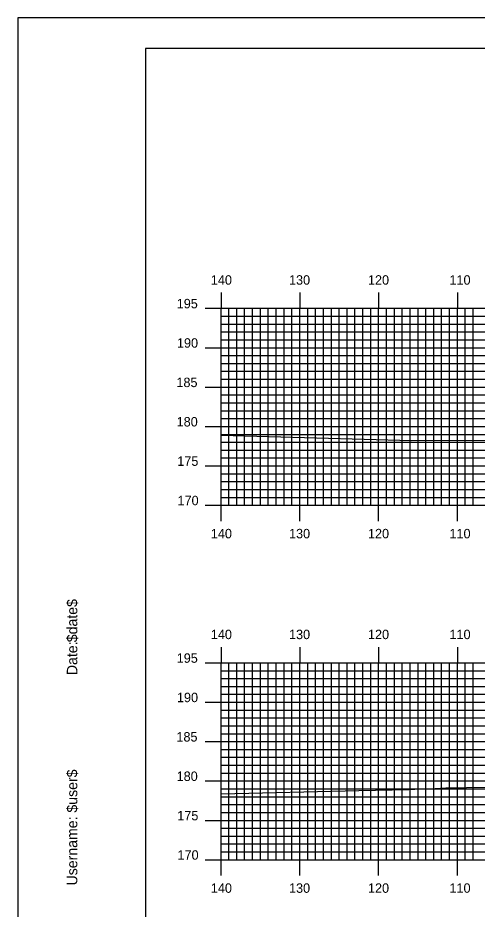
# Model space of a CAD drawing. Extents: x 1824360 to 1824703, y 442591 to 442811.
# Drawn here: x 1824359.5 to 1824417.8, y 442697.4 to 442810.5 of the extents above; entities that cross this region are included whole.
import ezdxf

# ---------------------------------------------------------------- set-up
doc = ezdxf.new("R2010")
doc.units = 0
for name, color, linetype in [('BORDER', 7, 'Continuous'), ('H_V ANNOTATION', 7, 'Continuous'), ('MAJOR', 7, 'Continuous'), ('MINOR', 7, 'Continuous'), ('PLOT BOUNDARY', 7, 'Continuous'), ('S_Roadway_Centerline', 7, 'Continuous')]:
    doc.layers.add(name, color=color, linetype=linetype)

msp = doc.modelspace()

# ---------------------------------------------------------------- linework, layer by layer
at = {"layer": 'BORDER'}
msp.add_lwpolyline([(1824375.73, 442596.67), (1824695.73, 442596.67), (1824695.73, 442806.67), (1824375.73, 442806.67)], close=True, dxfattribs=at)
at = {"layer": 'MAJOR'}
for p, q in [((1824385.33, 442775.67), (1824385.33, 442773.67)), ((1824395.33, 442775.67), (1824395.33, 442773.67)), ((1824405.33, 442775.67), (1824405.33, 442773.67)), ((1824415.33, 442775.67), (1824415.33, 442773.67)), ((1824383.33, 442773.67), (1824385.33, 442773.67)), ((1824385.33, 442773.67), (1824665.33, 442773.67)), ((1824385.33, 442748.67), (1824385.33, 442773.67)), ((1824385.33, 442748.67), (1824385.33, 442773.67)), ((1824385.33, 442773.67), (1824665.33, 442773.67)), ((1824395.33, 442748.67), (1824395.33, 442773.67)), ((1824405.33, 442748.67), (1824405.33, 442773.67)), ((1824415.33, 442748.67), (1824415.33, 442773.67)), ((1824383.33, 442768.67), (1824385.33, 442768.67)), ((1824385.33, 442768.67), (1824665.33, 442768.67)), ((1824383.33, 442763.67), (1824385.33, 442763.67)), ((1824385.33, 442763.67), (1824665.33, 442763.67)), ((1824383.33, 442758.67), (1824385.33, 442758.67)), ((1824385.33, 442758.67), (1824665.33, 442758.67)), ((1824383.33, 442753.67), (1824385.33, 442753.67)), ((1824385.33, 442753.67), (1824665.33, 442753.67)), ((1824383.33, 442748.67), (1824385.33, 442748.67)), ((1824385.33, 442748.67), (1824665.33, 442748.67)), ((1824385.33, 442748.67), (1824665.33, 442748.67)), ((1824385.33, 442746.66), (1824385.33, 442748.67)), ((1824395.33, 442746.66), (1824395.33, 442748.67)), ((1824405.33, 442746.66), (1824405.33, 442748.67)), ((1824415.33, 442746.66), (1824415.33, 442748.67)), ((1824385.33, 442730.67), (1824385.33, 442728.67)), ((1824395.33, 442730.67), (1824395.33, 442728.67)), ((1824405.33, 442730.67), (1824405.33, 442728.67)), ((1824415.33, 442730.67), (1824415.33, 442728.67)), ((1824383.33, 442728.67), (1824385.33, 442728.67)), ((1824385.33, 442728.67), (1824665.33, 442728.67)), ((1824385.33, 442703.67), (1824385.33, 442728.67)), ((1824385.33, 442703.67), (1824385.33, 442728.67)), ((1824385.33, 442728.67), (1824665.33, 442728.67)), ((1824395.33, 442703.67), (1824395.33, 442728.67)), ((1824405.33, 442703.67), (1824405.33, 442728.67)), ((1824415.33, 442703.67), (1824415.33, 442728.67)), ((1824383.33, 442723.67), (1824385.33, 442723.67)), ((1824385.33, 442723.67), (1824665.33, 442723.67)), ((1824383.33, 442718.67), (1824385.33, 442718.67)), ((1824385.33, 442718.67), (1824665.33, 442718.67)), ((1824383.33, 442713.67), (1824385.33, 442713.67)), ((1824385.33, 442713.67), (1824665.33, 442713.67)), ((1824383.33, 442708.67), (1824385.33, 442708.67)), ((1824385.33, 442708.67), (1824665.33, 442708.67)), ((1824383.33, 442703.67), (1824385.33, 442703.67)), ((1824385.33, 442703.67), (1824665.33, 442703.67)), ((1824385.33, 442703.67), (1824665.33, 442703.67)), ((1824385.33, 442701.66), (1824385.33, 442703.67)), ((1824395.33, 442701.66), (1824395.33, 442703.67)), ((1824405.33, 442701.66), (1824405.33, 442703.67)), ((1824415.33, 442701.66), (1824415.33, 442703.67))]:
    msp.add_line(p, q, dxfattribs=at)
at = {"layer": 'MINOR'}
for p, q in [((1824385.33, 442772.67), (1824665.33, 442772.67)), ((1824385.33, 442772.67), (1824387.34, 442772.67)), ((1824386.33, 442748.67), (1824386.33, 442773.67)), ((1824387.33, 442748.67), (1824387.33, 442773.67)), ((1824388.33, 442748.67), (1824388.33, 442773.67)), ((1824389.33, 442748.67), (1824389.33, 442773.67)), ((1824390.33, 442748.67), (1824390.33, 442773.67)), ((1824391.33, 442748.67), (1824391.33, 442773.67)), ((1824392.33, 442748.67), (1824392.33, 442773.67)), ((1824393.33, 442748.67), (1824393.33, 442773.67)), ((1824394.33, 442748.67), (1824394.33, 442773.67)), ((1824396.33, 442748.67), (1824396.33, 442773.67)), ((1824397.33, 442748.67), (1824397.33, 442773.67)), ((1824398.33, 442748.67), (1824398.33, 442773.67)), ((1824399.33, 442748.67), (1824399.33, 442773.67)), ((1824400.33, 442748.67), (1824400.33, 442773.67)), ((1824401.33, 442748.67), (1824401.33, 442773.67)), ((1824402.33, 442748.67), (1824402.33, 442773.67)), ((1824403.33, 442748.67), (1824403.33, 442773.67)), ((1824404.33, 442748.67), (1824404.33, 442773.67)), ((1824406.33, 442748.67), (1824406.33, 442773.67)), ((1824407.33, 442748.67), (1824407.33, 442773.67)), ((1824408.33, 442748.67), (1824408.33, 442773.67)), ((1824409.33, 442748.67), (1824409.33, 442773.67)), ((1824410.33, 442748.67), (1824410.33, 442773.67)), ((1824411.33, 442748.67), (1824411.33, 442773.67)), ((1824412.33, 442748.67), (1824412.33, 442773.67)), ((1824413.33, 442748.67), (1824413.33, 442773.67)), ((1824414.33, 442748.67), (1824414.33, 442773.67)), ((1824416.33, 442748.67), (1824416.33, 442773.67)), ((1824417.33, 442748.67), (1824417.33, 442773.67)), ((1824385.33, 442771.67), (1824665.33, 442771.67)), ((1824385.33, 442771.67), (1824387.34, 442771.67)), ((1824385.33, 442770.67), (1824665.33, 442770.67)), ((1824385.33, 442770.67), (1824387.34, 442770.67)), ((1824385.33, 442769.67), (1824665.33, 442769.67)), ((1824385.33, 442769.67), (1824387.34, 442769.67)), ((1824385.33, 442767.67), (1824665.33, 442767.67)), ((1824385.33, 442767.67), (1824387.34, 442767.67)), ((1824385.33, 442766.67), (1824665.33, 442766.67)), ((1824385.33, 442766.67), (1824387.34, 442766.67)), ((1824385.33, 442765.67), (1824665.33, 442765.67)), ((1824385.33, 442765.67), (1824387.34, 442765.67)), ((1824385.33, 442764.67), (1824665.33, 442764.67)), ((1824385.33, 442764.67), (1824387.34, 442764.67)), ((1824385.33, 442762.67), (1824665.33, 442762.67)), ((1824385.33, 442762.67), (1824387.34, 442762.67)), ((1824385.33, 442761.67), (1824665.33, 442761.67)), ((1824385.33, 442761.67), (1824387.34, 442761.67)), ((1824385.33, 442760.67), (1824665.33, 442760.67)), ((1824385.33, 442760.67), (1824387.34, 442760.67)), ((1824385.33, 442759.67), (1824665.33, 442759.67)), ((1824385.33, 442759.67), (1824387.34, 442759.67)), ((1824385.33, 442757.67), (1824665.33, 442757.67)), ((1824385.33, 442757.67), (1824387.34, 442757.67)), ((1824385.33, 442756.67), (1824665.33, 442756.67)), ((1824385.33, 442756.67), (1824387.34, 442756.67)), ((1824385.33, 442755.67), (1824665.33, 442755.67)), ((1824385.33, 442755.67), (1824387.34, 442755.67)), ((1824385.33, 442754.67), (1824665.33, 442754.67)), ((1824385.33, 442754.67), (1824387.34, 442754.67)), ((1824385.33, 442752.67), (1824665.33, 442752.67)), ((1824385.33, 442752.67), (1824387.34, 442752.67)), ((1824385.33, 442751.67), (1824665.33, 442751.67)), ((1824385.33, 442751.67), (1824387.34, 442751.67)), ((1824385.33, 442750.67), (1824665.33, 442750.67)), ((1824385.33, 442750.67), (1824387.34, 442750.67)), ((1824385.33, 442749.67), (1824665.33, 442749.67)), ((1824385.33, 442749.67), (1824387.34, 442749.67)), ((1824386.33, 442703.67), (1824386.33, 442728.67)), ((1824387.33, 442703.67), (1824387.33, 442728.67)), ((1824388.33, 442703.67), (1824388.33, 442728.67)), ((1824389.33, 442703.67), (1824389.33, 442728.67)), ((1824390.33, 442703.67), (1824390.33, 442728.67)), ((1824391.33, 442703.67), (1824391.33, 442728.67)), ((1824392.33, 442703.67), (1824392.33, 442728.67)), ((1824393.33, 442703.67), (1824393.33, 442728.67)), ((1824394.33, 442703.67), (1824394.33, 442728.67)), ((1824396.33, 442703.67), (1824396.33, 442728.67)), ((1824397.33, 442703.67), (1824397.33, 442728.67)), ((1824398.33, 442703.67), (1824398.33, 442728.67)), ((1824399.33, 442703.67), (1824399.33, 442728.67)), ((1824400.33, 442703.67), (1824400.33, 442728.67)), ((1824401.33, 442703.67), (1824401.33, 442728.67)), ((1824402.33, 442703.67), (1824402.33, 442728.67)), ((1824403.33, 442703.67), (1824403.33, 442728.67)), ((1824404.33, 442703.67), (1824404.33, 442728.67)), ((1824406.33, 442703.67), (1824406.33, 442728.67)), ((1824407.33, 442703.67), (1824407.33, 442728.67)), ((1824408.33, 442703.67), (1824408.33, 442728.67)), ((1824409.33, 442703.67), (1824409.33, 442728.67)), ((1824410.33, 442703.67), (1824410.33, 442728.67)), ((1824411.33, 442703.67), (1824411.33, 442728.67)), ((1824412.33, 442703.67), (1824412.33, 442728.67)), ((1824413.33, 442703.67), (1824413.33, 442728.67)), ((1824414.33, 442703.67), (1824414.33, 442728.67)), ((1824416.33, 442703.67), (1824416.33, 442728.67)), ((1824417.33, 442703.67), (1824417.33, 442728.67)), ((1824385.33, 442727.67), (1824665.33, 442727.67)), ((1824385.33, 442727.67), (1824387.34, 442727.67)), ((1824385.33, 442726.67), (1824665.33, 442726.67)), ((1824385.33, 442726.67), (1824387.34, 442726.67)), ((1824385.33, 442725.67), (1824665.33, 442725.67)), ((1824385.33, 442725.67), (1824387.34, 442725.67)), ((1824385.33, 442724.67), (1824665.33, 442724.67)), ((1824385.33, 442724.67), (1824387.34, 442724.67)), ((1824385.33, 442722.67), (1824665.33, 442722.67)), ((1824385.33, 442722.67), (1824387.34, 442722.67)), ((1824385.33, 442721.67), (1824665.33, 442721.67)), ((1824385.33, 442721.67), (1824387.34, 442721.67)), ((1824385.33, 442720.67), (1824665.33, 442720.67)), ((1824385.33, 442720.67), (1824387.34, 442720.67)), ((1824385.33, 442719.67), (1824665.33, 442719.67)), ((1824385.33, 442719.67), (1824387.34, 442719.67)), ((1824385.33, 442717.67), (1824665.33, 442717.67)), ((1824385.33, 442717.67), (1824387.34, 442717.67)), ((1824385.33, 442716.67), (1824665.33, 442716.67)), ((1824385.33, 442716.67), (1824387.34, 442716.67)), ((1824385.33, 442715.67), (1824665.33, 442715.67)), ((1824385.33, 442715.67), (1824387.34, 442715.67)), ((1824385.33, 442714.67), (1824665.33, 442714.67)), ((1824385.33, 442714.67), (1824387.34, 442714.67)), ((1824385.33, 442712.67), (1824665.33, 442712.67)), ((1824385.33, 442712.67), (1824387.34, 442712.67)), ((1824385.33, 442711.67), (1824665.33, 442711.67)), ((1824385.33, 442711.67), (1824387.34, 442711.67)), ((1824385.33, 442710.67), (1824665.33, 442710.67)), ((1824385.33, 442710.67), (1824387.34, 442710.67)), ((1824385.33, 442709.67), (1824665.33, 442709.67)), ((1824385.33, 442709.67), (1824387.34, 442709.67)), ((1824385.33, 442707.67), (1824665.33, 442707.67)), ((1824385.33, 442707.67), (1824387.34, 442707.67)), ((1824385.33, 442706.67), (1824665.33, 442706.67)), ((1824385.33, 442706.67), (1824387.34, 442706.67)), ((1824385.33, 442705.67), (1824665.33, 442705.67)), ((1824385.33, 442705.67), (1824387.34, 442705.67)), ((1824385.33, 442704.67), (1824665.33, 442704.67)), ((1824385.33, 442704.67), (1824387.34, 442704.67))]:
    msp.add_line(p, q, dxfattribs=at)
at = {"layer": 'PLOT BOUNDARY'}
msp.add_lwpolyline([(1824359.55, 442590.55), (1824699.55, 442590.55), (1824699.55, 442810.55), (1824359.55, 442810.55)], close=True, dxfattribs=at)
at = {"layer": 'S_Roadway_Centerline'}
for points in [[(1824385.33, 442757.56), (1824409.53, 442756.89), (1824421.89, 442756.92), (1824434.26, 442757.04), (1824451.72, 442757.05), (1824453.76, 442757.05), (1824465.17, 442757.54), (1824467.57, 442757.66), (1824470.41, 442758.06), (1824470.83, 442758.09), (1824478.1, 442759.03)], [(1824385.33, 442712.03), (1824402.82, 442712.45), (1824409.16, 442712.57), (1824410.67, 442712.68), (1824412.52, 442712.73), (1824413.87, 442712.78), (1824437.61, 442713.18), (1824464.29, 442713.59), (1824464.6, 442713.6), (1824466.33, 442713.49), (1824471.62, 442713.65), (1824477.58, 442714.21)]]:
    msp.add_lwpolyline(points, dxfattribs=at)

# ---------------------------------------------------------------- texts
at = {"layer": 'BORDER'}
for s, p in [('$date$', (1824367.1, 442731.28)), ('Date:', (1824367.1, 442727.1)), ('$user$', (1824367.1, 442709.65)), ('Username:', (1824367.1, 442700.4))]:
    msp.add_text(s, height=1.339, rotation=90, dxfattribs=at).set_placement(p)
at = {"layer": 'H_V ANNOTATION'}
for s, p in [('140', (1824384.04, 442776.67)), ('130', (1824393.96, 442776.67)), ('120', (1824403.98, 442776.67)), ('110', (1824414.32, 442776.67)), ('195', (1824379.71, 442773.67)), ('190', (1824379.74, 442768.67)), ('185', (1824379.67, 442763.67)), ('180', (1824379.7, 442758.67)), ('175', (1824379.78, 442753.67)), ('170', (1824379.81, 442748.67)), ('140', (1824384.04, 442744.47)), ('130', (1824393.96, 442744.47)), ('120', (1824403.98, 442744.47)), ('110', (1824414.32, 442744.47)), ('140', (1824384.04, 442731.67)), ('130', (1824393.96, 442731.67)), ('120', (1824403.98, 442731.67)), ('110', (1824414.32, 442731.67)), ('195', (1824379.71, 442728.67)), ('190', (1824379.74, 442723.67)), ('185', (1824379.67, 442718.67)), ('180', (1824379.7, 442713.67)), ('175', (1824379.78, 442708.67)), ('170', (1824379.81, 442703.67)), ('140', (1824384.04, 442699.47)), ('130', (1824393.96, 442699.47)), ('120', (1824403.98, 442699.47)), ('110', (1824414.32, 442699.47))]:
    msp.add_text(s, height=1.2, dxfattribs=at).set_placement(p)
at = {"layer": 'MAJOR'}
for p in [(1824385.33, 442748.67), (1824385.33, 442703.67)]:
    msp.add_text('-', height=0.012, dxfattribs=at).set_placement(p)

doc.saveas('drawing.dxf')
